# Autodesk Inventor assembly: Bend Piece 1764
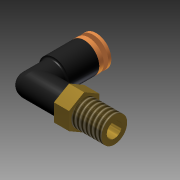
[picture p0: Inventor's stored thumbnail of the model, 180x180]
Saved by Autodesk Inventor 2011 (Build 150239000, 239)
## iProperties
Created: 2010-02
Part Number: Bend Piece 1764
Document SubType Name: Assembly
Designer: jgehrig
Author: jgehrig
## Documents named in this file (4)
- R:\CAD Archives\Pneumatics\Pnewmatics Bend Piece 1764\Pneumatic Bend Piece 1764.iam
- R:\CAD Archives\Pneumatics\Pnewmatics Bend Piece 1764\Pneumatic Screw Part 1764.ipt
- R:\CAD Archives\Pneumatics\Pnewmatics Bend Piece 1764\Pneumatic Screw Part 2 1764.ipt
- R:\CAD Archives\Pneumatics\Pnewmatics Bend Piece 1764\Pneumatic Bend Piece 1764.ipt
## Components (3 placed, 3 different names)
1. Pneumatic Bend Piece 1764:1 — Insert:1, Insert:2
2. Pneumatic Screw Part 1764:1 — Insert:2
3. Pneumatic Screw Part 2 1764:1 — Insert:1
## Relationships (2: Insert 2)
- Insert:1: Pneumatic Bend Piece 1764:1 ↔ Pneumatic Screw Part 2 1764:1
- Insert:2: Pneumatic Bend Piece 1764:1 ↔ Pneumatic Screw Part 1764:1
